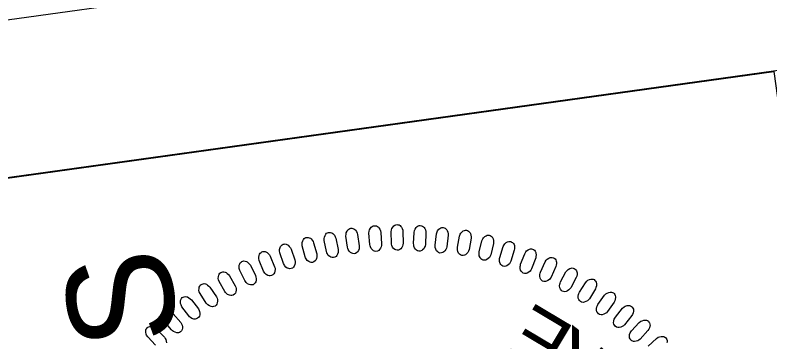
# Model space of a CAD drawing. Extents: x 477151 to 478666, y 496366 to 498184.
# Drawn here: x 477440.5 to 477522.5, y 498010.8 to 498046.4 of the extents above; entities that cross this region are included whole.
import ezdxf

# ---------------------------------------------------------------- set-up
doc = ezdxf.new("R2010")
doc.units = 0
for name, color, linetype in [('Sheet PE Seal Cell', 7, 'Continuous'), ('Sheet Plan CELL', 7, 'Continuous'), ('Sheet Plot Border Outside CELL', 7, 'Continuous'), ('Sheet Sticker Incomplete CELL', 7, 'Continuous')]:
    doc.layers.add(name, color=color, linetype=linetype)

msp = doc.modelspace()

# ---------------------------------------------------------------- linework, layer by layer
at = {"layer": 'Sheet PE Seal Cell'}
for points in [[(477476.574, 498021.127), (477476.405, 498022.343), (477476.412, 498022.565), (477476.445, 498022.71), (477476.533, 498022.894), (477476.613, 498023.016), (477476.714, 498023.11), (477476.812, 498023.164), (477476.921, 498023.199), (477477.034, 498023.195), (477477.157, 498023.182), (477477.268, 498023.137), (477477.386, 498023.052), (477477.456, 498022.981), (477477.544, 498022.842), (477477.627, 498022.673), (477477.671, 498022.518), (477477.852, 498021.274), (477477.853, 498021.104), (477477.827, 498020.959), (477477.76, 498020.788), (477477.669, 498020.635), (477477.584, 498020.542), (477477.436, 498020.461), (477477.291, 498020.421), (477477.137, 498020.44), (477477.027, 498020.475), (477476.887, 498020.556), (477476.746, 498020.708), (477476.654, 498020.877), (477476.607, 498021.001)], [(477478.996, 498021.431), (477478.904, 498022.654), (477478.925, 498022.875), (477478.966, 498023.019), (477479.065, 498023.197), (477479.154, 498023.313), (477479.26, 498023.401), (477479.361, 498023.448), (477479.472, 498023.477), (477479.585, 498023.465), (477479.706, 498023.445), (477479.815, 498023.393), (477479.927, 498023.301), (477479.992, 498023.226), (477480.071, 498023.082), (477480.144, 498022.907), (477480.178, 498022.75), (477480.28, 498021.497), (477480.27, 498021.327), (477480.236, 498021.184), (477480.159, 498021.018), (477480.057, 498020.871), (477479.967, 498020.783), (477479.814, 498020.712), (477479.666, 498020.681), (477479.515, 498020.71), (477479.407, 498020.752), (477479.273, 498020.841), (477479.141, 498021.001), (477479.06, 498021.176), (477479.021, 498021.302)], [(477481.336, 498021.588), (477481.321, 498022.815), (477481.356, 498023.035), (477481.406, 498023.175), (477481.516, 498023.347), (477481.612, 498023.457), (477481.723, 498023.538), (477481.827, 498023.579), (477481.94, 498023.6), (477482.052, 498023.582), (477482.172, 498023.553), (477482.277, 498023.495), (477482.383, 498023.397), (477482.444, 498023.318), (477482.513, 498023.169), (477482.575, 498022.99), (477482.599, 498022.831), (477482.622, 498021.574), (477482.602, 498021.404), (477482.558, 498021.264), (477482.471, 498021.104), (477482.361, 498020.963), (477482.264, 498020.882), (477482.108, 498020.82), (477481.959, 498020.798), (477481.809, 498020.837), (477481.704, 498020.885), (477481.575, 498020.983), (477481.454, 498021.151), (477481.384, 498021.33), (477481.353, 498021.459)], [(477483.755, 498021.524), (477483.818, 498022.749), (477483.866, 498022.966), (477483.924, 498023.103), (477484.046, 498023.267), (477484.148, 498023.372), (477484.264, 498023.446), (477484.371, 498023.48), (477484.484, 498023.495), (477484.595, 498023.469), (477484.713, 498023.433), (477484.814, 498023.368), (477484.913, 498023.263), (477484.97, 498023.18), (477485.029, 498023.028), (477485.08, 498022.845), (477485.094, 498022.685), (477485.038, 498021.43), (477485.007, 498021.261), (477484.955, 498021.124), (477484.857, 498020.97), (477484.738, 498020.836), (477484.637, 498020.761), (477484.478, 498020.709), (477484.327, 498020.697), (477484.18, 498020.744), (477484.078, 498020.799), (477483.956, 498020.905), (477483.845, 498021.08), (477483.787, 498021.264), (477483.764, 498021.394)], [(477486.099, 498021.365), (477486.238, 498022.584), (477486.3, 498022.797), (477486.367, 498022.93), (477486.498, 498023.086), (477486.607, 498023.184), (477486.728, 498023.251), (477486.836, 498023.278), (477486.95, 498023.285), (477487.058, 498023.253), (477487.174, 498023.209), (477487.272, 498023.139), (477487.364, 498023.027), (477487.415, 498022.942), (477487.464, 498022.785), (477487.504, 498022.6), (477487.508, 498022.439), (477487.373, 498021.19), (477487.331, 498021.023), (477487.271, 498020.89), (477487.164, 498020.742), (477487.037, 498020.616), (477486.932, 498020.547), (477486.768, 498020.506), (477486.618, 498020.503), (477486.474, 498020.559), (477486.375, 498020.621), (477486.26, 498020.734), (477486.161, 498020.916), (477486.114, 498021.103), (477486.1, 498021.234)], [(477488.522, 498021.124), (477488.737, 498022.332), (477488.812, 498022.541), (477488.888, 498022.67), (477489.028, 498022.817), (477489.143, 498022.908), (477489.268, 498022.967), (477489.378, 498022.988), (477489.491, 498022.987), (477489.598, 498022.948), (477489.711, 498022.897), (477489.803, 498022.821), (477489.889, 498022.704), (477489.934, 498022.615), (477489.973, 498022.456), (477490.001, 498022.269), (477489.996, 498022.107), (477489.782, 498020.869), (477489.73, 498020.706), (477489.662, 498020.576), (477489.546, 498020.435), (477489.411, 498020.317), (477489.301, 498020.256), (477489.136, 498020.224), (477488.985, 498020.231), (477488.845, 498020.297), (477488.751, 498020.364), (477488.643, 498020.484), (477488.556, 498020.672), (477488.521, 498020.861), (477488.514, 498020.993)], [(477471.978, 498020.091), (477471.659, 498021.276), (477471.637, 498021.497), (477471.651, 498021.645), (477471.715, 498021.838), (477471.78, 498021.97), (477471.868, 498022.076), (477471.958, 498022.142), (477472.061, 498022.19), (477472.175, 498022.2), (477472.299, 498022.202), (477472.415, 498022.172), (477472.542, 498022.103), (477472.62, 498022.042), (477472.724, 498021.914), (477472.829, 498021.757), (477472.893, 498021.608), (477473.227, 498020.397), (477473.249, 498020.228), (477473.242, 498020.081), (477473.197, 498019.904), (477473.126, 498019.74), (477473.052, 498019.637), (477472.917, 498019.538), (477472.777, 498019.481), (477472.623, 498019.48), (477472.509, 498019.501), (477472.36, 498019.564), (477472.2, 498019.697), (477472.089, 498019.853), (477472.026, 498019.97)], [(477474.286, 498020.658), (477474.042, 498021.861), (477474.035, 498022.083), (477474.058, 498022.23), (477474.134, 498022.419), (477474.208, 498022.545), (477474.302, 498022.646), (477474.396, 498022.705), (477474.502, 498022.748), (477474.616, 498022.751), (477474.739, 498022.745), (477474.853, 498022.707), (477474.976, 498022.631), (477475.05, 498022.564), (477475.147, 498022.431), (477475.241, 498022.267), (477475.294, 498022.115), (477475.552, 498020.885), (477475.564, 498020.715), (477475.548, 498020.569), (477475.492, 498020.395), (477475.41, 498020.236), (477475.331, 498020.138), (477475.189, 498020.048), (477475.046, 498019.999), (477474.892, 498020.008), (477474.779, 498020.036), (477474.635, 498020.108), (477474.484, 498020.25), (477474.382, 498020.413), (477474.327, 498020.534)], [(477490.889, 498020.644), (477491.179, 498021.836), (477491.268, 498022.04), (477491.351, 498022.164), (477491.501, 498022.302), (477491.621, 498022.386), (477491.749, 498022.436), (477491.86, 498022.45), (477491.973, 498022.443), (477492.078, 498022.397), (477492.187, 498022.34), (477492.274, 498022.257), (477492.352, 498022.135), (477492.392, 498022.043), (477492.421, 498021.882), (477492.437, 498021.694), (477492.421, 498021.534), (477492.131, 498020.311), (477492.069, 498020.152), (477491.992, 498020.026), (477491.867, 498019.893), (477491.726, 498019.783), (477491.612, 498019.729), (477491.445, 498019.708), (477491.295, 498019.724), (477491.159, 498019.798), (477491.07, 498019.872), (477490.969, 498019.998), (477490.894, 498020.191), (477490.871, 498020.382), (477490.873, 498020.515)], [(477469.617, 498019.361), (477469.224, 498020.522), (477469.189, 498020.742), (477469.193, 498020.891), (477469.245, 498021.088), (477469.302, 498021.223), (477469.383, 498021.335), (477469.469, 498021.406), (477469.569, 498021.461), (477469.681, 498021.478), (477469.805, 498021.487), (477469.922, 498021.465), (477470.053, 498021.404), (477470.136, 498021.348), (477470.248, 498021.227), (477470.362, 498021.076), (477470.434, 498020.933), (477470.844, 498019.744), (477470.877, 498019.576), (477470.879, 498019.43), (477470.845, 498019.25), (477470.784, 498019.082), (477470.718, 498018.976), (477470.588, 498018.868), (477470.453, 498018.802), (477470.299, 498018.791), (477470.184, 498018.805), (477470.031, 498018.858), (477469.864, 498018.981), (477469.742, 498019.13), (477469.673, 498019.243)], [(477493.113, 498020.023), (477493.478, 498021.194), (477493.579, 498021.392), (477493.67, 498021.51), (477493.828, 498021.639), (477493.953, 498021.715), (477494.084, 498021.758), (477494.196, 498021.764), (477494.308, 498021.75), (477494.409, 498021.698), (477494.515, 498021.633), (477494.597, 498021.545), (477494.667, 498021.419), (477494.701, 498021.325), (477494.721, 498021.162), (477494.724, 498020.973), (477494.698, 498020.814), (477494.332, 498019.612), (477494.26, 498019.457), (477494.175, 498019.337), (477494.042, 498019.211), (477493.894, 498019.111), (477493.778, 498019.064), (477493.61, 498019.054), (477493.461, 498019.079), (477493.33, 498019.161), (477493.245, 498019.241), (477493.153, 498019.373), (477493.09, 498019.571), (477493.079, 498019.762), (477493.089, 498019.894)], [(477467.454, 498018.545), (477466.989, 498019.68), (477466.941, 498019.897), (477466.935, 498020.046), (477466.975, 498020.246), (477467.023, 498020.384), (477467.097, 498020.5), (477467.178, 498020.577), (477467.275, 498020.638), (477467.386, 498020.662), (477467.508, 498020.68), (477467.627, 498020.665), (477467.762, 498020.612), (477467.848, 498020.561), (477467.966, 498020.448), (477468.09, 498020.304), (477468.171, 498020.165), (477468.655, 498019.005), (477468.699, 498018.84), (477468.71, 498018.694), (477468.688, 498018.512), (477468.637, 498018.341), (477468.578, 498018.23), (477468.455, 498018.115), (477468.324, 498018.04), (477468.171, 498018.02), (477468.055, 498018.026), (477467.9, 498018.07), (477467.725, 498018.181), (477467.594, 498018.322), (477467.517, 498018.431)], [(477495.385, 498019.28), (477495.822, 498020.426), (477495.936, 498020.617), (477496.034, 498020.73), (477496.2, 498020.848), (477496.33, 498020.916), (477496.463, 498020.95), (477496.575, 498020.951), (477496.687, 498020.929), (477496.784, 498020.871), (477496.885, 498020.799), (477496.961, 498020.707), (477497.024, 498020.576), (477497.051, 498020.48), (477497.061, 498020.316), (477497.052, 498020.127), (477497.017, 498019.971), (477496.576, 498018.793), (477496.494, 498018.643), (477496.402, 498018.529), (477496.262, 498018.412), (477496.107, 498018.321), (477495.988, 498018.282), (477495.82, 498018.281), (477495.673, 498018.316), (477495.548, 498018.407), (477495.468, 498018.491), (477495.384, 498018.629), (477495.333, 498018.83), (477495.335, 498019.022), (477495.352, 498019.154)], [(477465.405, 498017.508), (477464.869, 498018.612), (477464.807, 498018.825), (477464.792, 498018.974), (477464.819, 498019.175), (477464.858, 498019.316), (477464.925, 498019.437), (477465.001, 498019.518), (477465.094, 498019.585), (477465.203, 498019.616), (477465.324, 498019.642), (477465.444, 498019.634), (477465.582, 498019.589), (477465.67, 498019.544), (477465.797, 498019.439), (477465.929, 498019.304), (477466.019, 498019.17), (477466.575, 498018.043), (477466.628, 498017.881), (477466.648, 498017.735), (477466.638, 498017.553), (477466.598, 498017.378), (477466.545, 498017.264), (477466.43, 498017.141), (477466.305, 498017.058), (477466.152, 498017.029), (477466.037, 498017.028), (477465.879, 498017.062), (477465.697, 498017.162), (477465.558, 498017.294), (477465.475, 498017.398)], [(477497.534, 498018.431), (477498.043, 498019.548), (477498.168, 498019.732), (477498.273, 498019.838), (477498.446, 498019.945), (477498.579, 498020.005), (477498.715, 498020.031), (477498.826, 498020.024), (477498.937, 498019.995), (477499.03, 498019.931), (477499.127, 498019.854), (477499.197, 498019.756), (477499.251, 498019.622), (477499.273, 498019.524), (477499.272, 498019.36), (477499.252, 498019.172), (477499.206, 498019.018), (477498.691, 498017.871), (477498.601, 498017.726), (477498.502, 498017.618), (477498.355, 498017.51), (477498.195, 498017.429), (477498.073, 498017.397), (477497.905, 498017.408), (477497.761, 498017.452), (477497.642, 498017.55), (477497.567, 498017.639), (477497.492, 498017.782), (477497.454, 498017.986), (477497.467, 498018.177), (477497.494, 498018.307)], [(477499.718, 498017.362), (477500.296, 498018.443), (477500.433, 498018.619), (477500.544, 498018.719), (477500.723, 498018.815), (477500.86, 498018.866), (477500.997, 498018.884), (477501.108, 498018.87), (477501.216, 498018.834), (477501.305, 498018.764), (477501.397, 498018.681), (477501.461, 498018.58), (477501.506, 498018.442), (477501.522, 498018.343), (477501.511, 498018.18), (477501.479, 498017.993), (477501.424, 498017.841), (477500.839, 498016.73), (477500.739, 498016.591), (477500.633, 498016.489), (477500.479, 498016.39), (477500.315, 498016.32), (477500.191, 498016.295), (477500.024, 498016.316), (477499.883, 498016.369), (477499.77, 498016.474), (477499.701, 498016.568), (477499.636, 498016.716), (477499.61, 498016.921), (477499.636, 498017.112), (477499.67, 498017.24)], [(477463.233, 498016.323), (477462.629, 498017.391), (477462.554, 498017.6), (477462.53, 498017.747), (477462.544, 498017.95), (477462.575, 498018.093), (477462.633, 498018.218), (477462.704, 498018.304), (477462.792, 498018.377), (477462.9, 498018.414), (477463.019, 498018.447), (477463.139, 498018.447), (477463.28, 498018.411), (477463.371, 498018.372), (477463.503, 498018.275), (477463.644, 498018.148), (477463.741, 498018.02), (477464.367, 498016.93), (477464.431, 498016.772), (477464.46, 498016.628), (477464.461, 498016.445), (477464.432, 498016.268), (477464.387, 498016.151), (477464.28, 498016.021), (477464.159, 498015.931), (477464.01, 498015.892), (477463.894, 498015.884), (477463.734, 498015.907), (477463.547, 498015.997), (477463.399, 498016.12), (477463.31, 498016.218)], [(477501.775, 498016.23), (477502.419, 498017.273), (477502.566, 498017.44), (477502.683, 498017.532), (477502.868, 498017.617), (477503.009, 498017.659), (477503.146, 498017.668), (477503.256, 498017.647), (477503.362, 498017.604), (477503.446, 498017.529), (477503.533, 498017.441), (477503.59, 498017.335), (477503.627, 498017.195), (477503.636, 498017.096), (477503.614, 498016.933), (477503.571, 498016.749), (477503.506, 498016.601), (477502.853, 498015.528), (477502.744, 498015.396), (477502.632, 498015.301), (477502.473, 498015.212), (477502.304, 498015.152), (477502.179, 498015.136), (477502.014, 498015.167), (477501.877, 498015.229), (477501.77, 498015.341), (477501.708, 498015.439), (477501.652, 498015.59), (477501.639, 498015.797), (477501.676, 498015.985), (477501.719, 498016.111)], [(477461.228, 498015.055), (477460.557, 498016.083), (477460.469, 498016.287), (477460.436, 498016.432), (477460.438, 498016.636), (477460.46, 498016.781), (477460.51, 498016.909), (477460.576, 498016.999), (477460.659, 498017.077), (477460.764, 498017.122), (477460.88, 498017.162), (477461, 498017.169), (477461.143, 498017.143), (477461.236, 498017.109), (477461.375, 498017.02), (477461.522, 498016.902), (477461.628, 498016.78), (477462.321, 498015.732), (477462.394, 498015.578), (477462.433, 498015.436), (477462.445, 498015.254), (477462.427, 498015.075), (477462.39, 498014.956), (477462.291, 498014.82), (477462.176, 498014.721), (477462.03, 498014.673), (477461.914, 498014.658), (477461.754, 498014.672), (477461.561, 498014.749), (477461.406, 498014.862), (477461.311, 498014.955)], [(477459.317, 498013.671), (477458.584, 498014.655), (477458.483, 498014.853), (477458.441, 498014.996), (477458.429, 498015.199), (477458.442, 498015.345), (477458.484, 498015.476), (477458.545, 498015.571), (477458.622, 498015.653), (477458.724, 498015.705), (477458.838, 498015.752), (477458.957, 498015.767), (477459.101, 498015.75), (477459.196, 498015.721), (477459.34, 498015.641), (477459.495, 498015.533), (477459.609, 498015.419), (477460.366, 498014.416), (477460.449, 498014.266), (477460.497, 498014.127), (477460.519, 498013.946), (477460.513, 498013.768), (477460.483, 498013.645), (477460.393, 498013.503), (477460.285, 498013.398), (477460.142, 498013.34), (477460.028, 498013.318), (477459.866, 498013.322), (477459.669, 498013.386), (477459.508, 498013.49), (477459.406, 498013.576)], [(477503.788, 498014.9), (477504.497, 498015.901), (477504.654, 498016.059), (477504.777, 498016.143), (477504.967, 498016.216), (477505.11, 498016.249), (477505.247, 498016.25), (477505.355, 498016.222), (477505.459, 498016.173), (477505.539, 498016.092), (477505.619, 498015.998), (477505.67, 498015.89), (477505.697, 498015.747), (477505.7, 498015.648), (477505.669, 498015.487), (477505.614, 498015.306), (477505.54, 498015.162), (477504.82, 498014.133), (477504.704, 498014.007), (477504.586, 498013.919), (477504.421, 498013.841), (477504.25, 498013.791), (477504.123, 498013.783), (477503.961, 498013.824), (477503.827, 498013.895), (477503.728, 498014.014), (477503.672, 498014.115), (477503.626, 498014.27), (477503.626, 498014.477), (477503.675, 498014.663), (477503.725, 498014.786)], [(477505.688, 498013.537), (477506.458, 498014.492), (477506.625, 498014.639), (477506.754, 498014.715), (477506.947, 498014.776), (477507.092, 498014.801), (477507.229, 498014.792), (477507.336, 498014.758), (477507.436, 498014.702), (477507.51, 498014.617), (477507.584, 498014.518), (477507.629, 498014.407), (477507.647, 498014.263), (477507.644, 498014.163), (477507.602, 498014.005), (477507.536, 498013.827), (477507.453, 498013.689), (477506.67, 498012.706), (477506.546, 498012.588), (477506.423, 498012.508), (477506.254, 498012.44), (477506.079, 498012.402), (477505.953, 498012.401), (477505.793, 498012.452), (477505.664, 498012.531), (477505.573, 498012.656), (477505.523, 498012.76), (477505.486, 498012.918), (477505.499, 498013.124), (477505.56, 498013.307), (477505.618, 498013.426)], [(477457.461, 498012.14), (477456.667, 498013.075), (477456.553, 498013.267), (477456.503, 498013.407), (477456.479, 498013.609), (477456.482, 498013.756), (477456.516, 498013.889), (477456.57, 498013.987), (477456.642, 498014.075), (477456.741, 498014.132), (477456.852, 498014.186), (477456.97, 498014.208), (477457.115, 498014.2), (477457.212, 498014.178), (477457.36, 498014.107), (477457.521, 498014.009), (477457.642, 498013.902), (477458.46, 498012.949), (477458.553, 498012.805), (477458.608, 498012.669), (477458.644, 498012.489), (477458.648, 498012.31), (477458.626, 498012.187), (477458.545, 498012.039), (477458.444, 498011.928), (477458.304, 498011.862), (477458.192, 498011.832), (477458.03, 498011.826), (477457.83, 498011.877), (477457.662, 498011.971), (477457.555, 498012.051)], [(477507.441, 498012.031), (477508.27, 498012.936), (477508.446, 498013.073), (477508.579, 498013.14), (477508.776, 498013.19), (477508.922, 498013.205), (477509.059, 498013.188), (477509.162, 498013.147), (477509.259, 498013.086), (477509.327, 498012.995), (477509.395, 498012.892), (477509.432, 498012.778), (477509.442, 498012.633), (477509.433, 498012.534), (477509.381, 498012.378), (477509.303, 498012.205), (477509.213, 498012.073), (477508.37, 498011.141), (477508.238, 498011.032), (477508.11, 498010.959), (477507.937, 498010.902), (477507.76, 498010.874), (477507.634, 498010.882), (477507.478, 498010.943), (477507.354, 498011.029), (477507.271, 498011.16), (477507.227, 498011.268), (477507.201, 498011.427), (477507.228, 498011.632), (477507.299, 498011.811), (477507.365, 498011.926)]]:
    msp.add_lwpolyline(points, close=True, dxfattribs=at)
for points in [[(477455.726, 498010.484), (477454.876, 498011.368), (477454.75, 498011.552), (477454.691, 498011.689), (477454.654, 498011.889), (477454.648, 498012.035), (477454.674, 498012.17), (477454.721, 498012.272), (477454.788, 498012.364), (477454.883, 498012.428), (477454.99, 498012.489), (477455.107, 498012.518), (477455.251, 498012.519), (477455.35, 498012.503), (477455.502, 498012.442), (477455.67, 498012.354), (477455.797, 498012.255), (477456.673, 498011.354), (477456.774, 498011.217), (477456.839, 498011.084), (477456.885, 498010.908), (477456.901, 498010.729)], [(477509.255, 498010.359), (477510.139, 498011.209), (477510.323, 498011.335), (477510.459, 498011.395), (477510.659, 498011.431), (477510.806, 498011.437), (477510.942, 498011.412), (477511.042, 498011.364), (477511.134, 498011.297), (477511.197, 498011.203), (477511.259, 498011.095), (477511.289, 498010.979), (477511.289, 498010.834), (477511.274, 498010.735)]]:
    msp.add_lwpolyline(points, dxfattribs=at)
at = {"layer": 'Sheet Plan CELL'}
for points in [[(477374.243, 498019.604), (477581.003, 496533.885), (478620.981, 496678.613), (478414.224, 498164.308)], [(477425.234, 497925.712), (477411.44, 498024.743), (477522.877, 498040.264), (477536.673, 497941.22)]]:
    msp.add_lwpolyline(points, close=True, dxfattribs=at)
at = {"layer": 'Sheet Plot Border Outside CELL'}
msp.add_lwpolyline([(478666.227, 496516.818), (478434.179, 498184.249), (477349.631, 498033.318), (477581.679, 496365.887)], close=True, dxfattribs=at)

# ---------------------------------------------------------------- texts
at = {"layer": 'Sheet PE Seal Cell'}
for s, rotation, p in [('E', 149.19094, (477501.475, 498012.29)), ('K', 142.34528, (477505.287, 498009.382))]:
    msp.add_text(s, height=6.236, rotation=rotation, dxfattribs=at).set_placement(p)
at = {"layer": 'Sheet Sticker Incomplete CELL'}
msp.add_text('INCOMPLETE PLANS', height=11.52, rotation=97.92268, dxfattribs=at).set_placement((477478.256, 497867.918))

doc.saveas('drawing.dxf')
